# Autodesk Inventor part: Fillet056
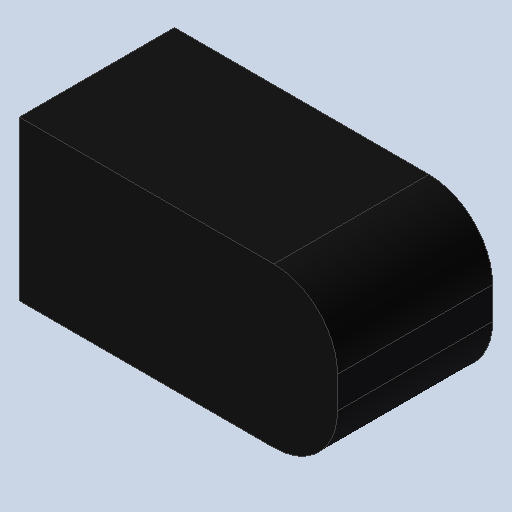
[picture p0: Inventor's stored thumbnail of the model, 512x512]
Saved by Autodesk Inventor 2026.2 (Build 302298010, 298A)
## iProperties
Created: 2026-10
Part Number: Fillet056
Material: Générique
Document SubType Name: Modeling
Designer: mel
Density: 1 g/cm^3
Appearance: Par défaut
Author: mel
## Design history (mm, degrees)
feature "Base1"
node "Solide1"
